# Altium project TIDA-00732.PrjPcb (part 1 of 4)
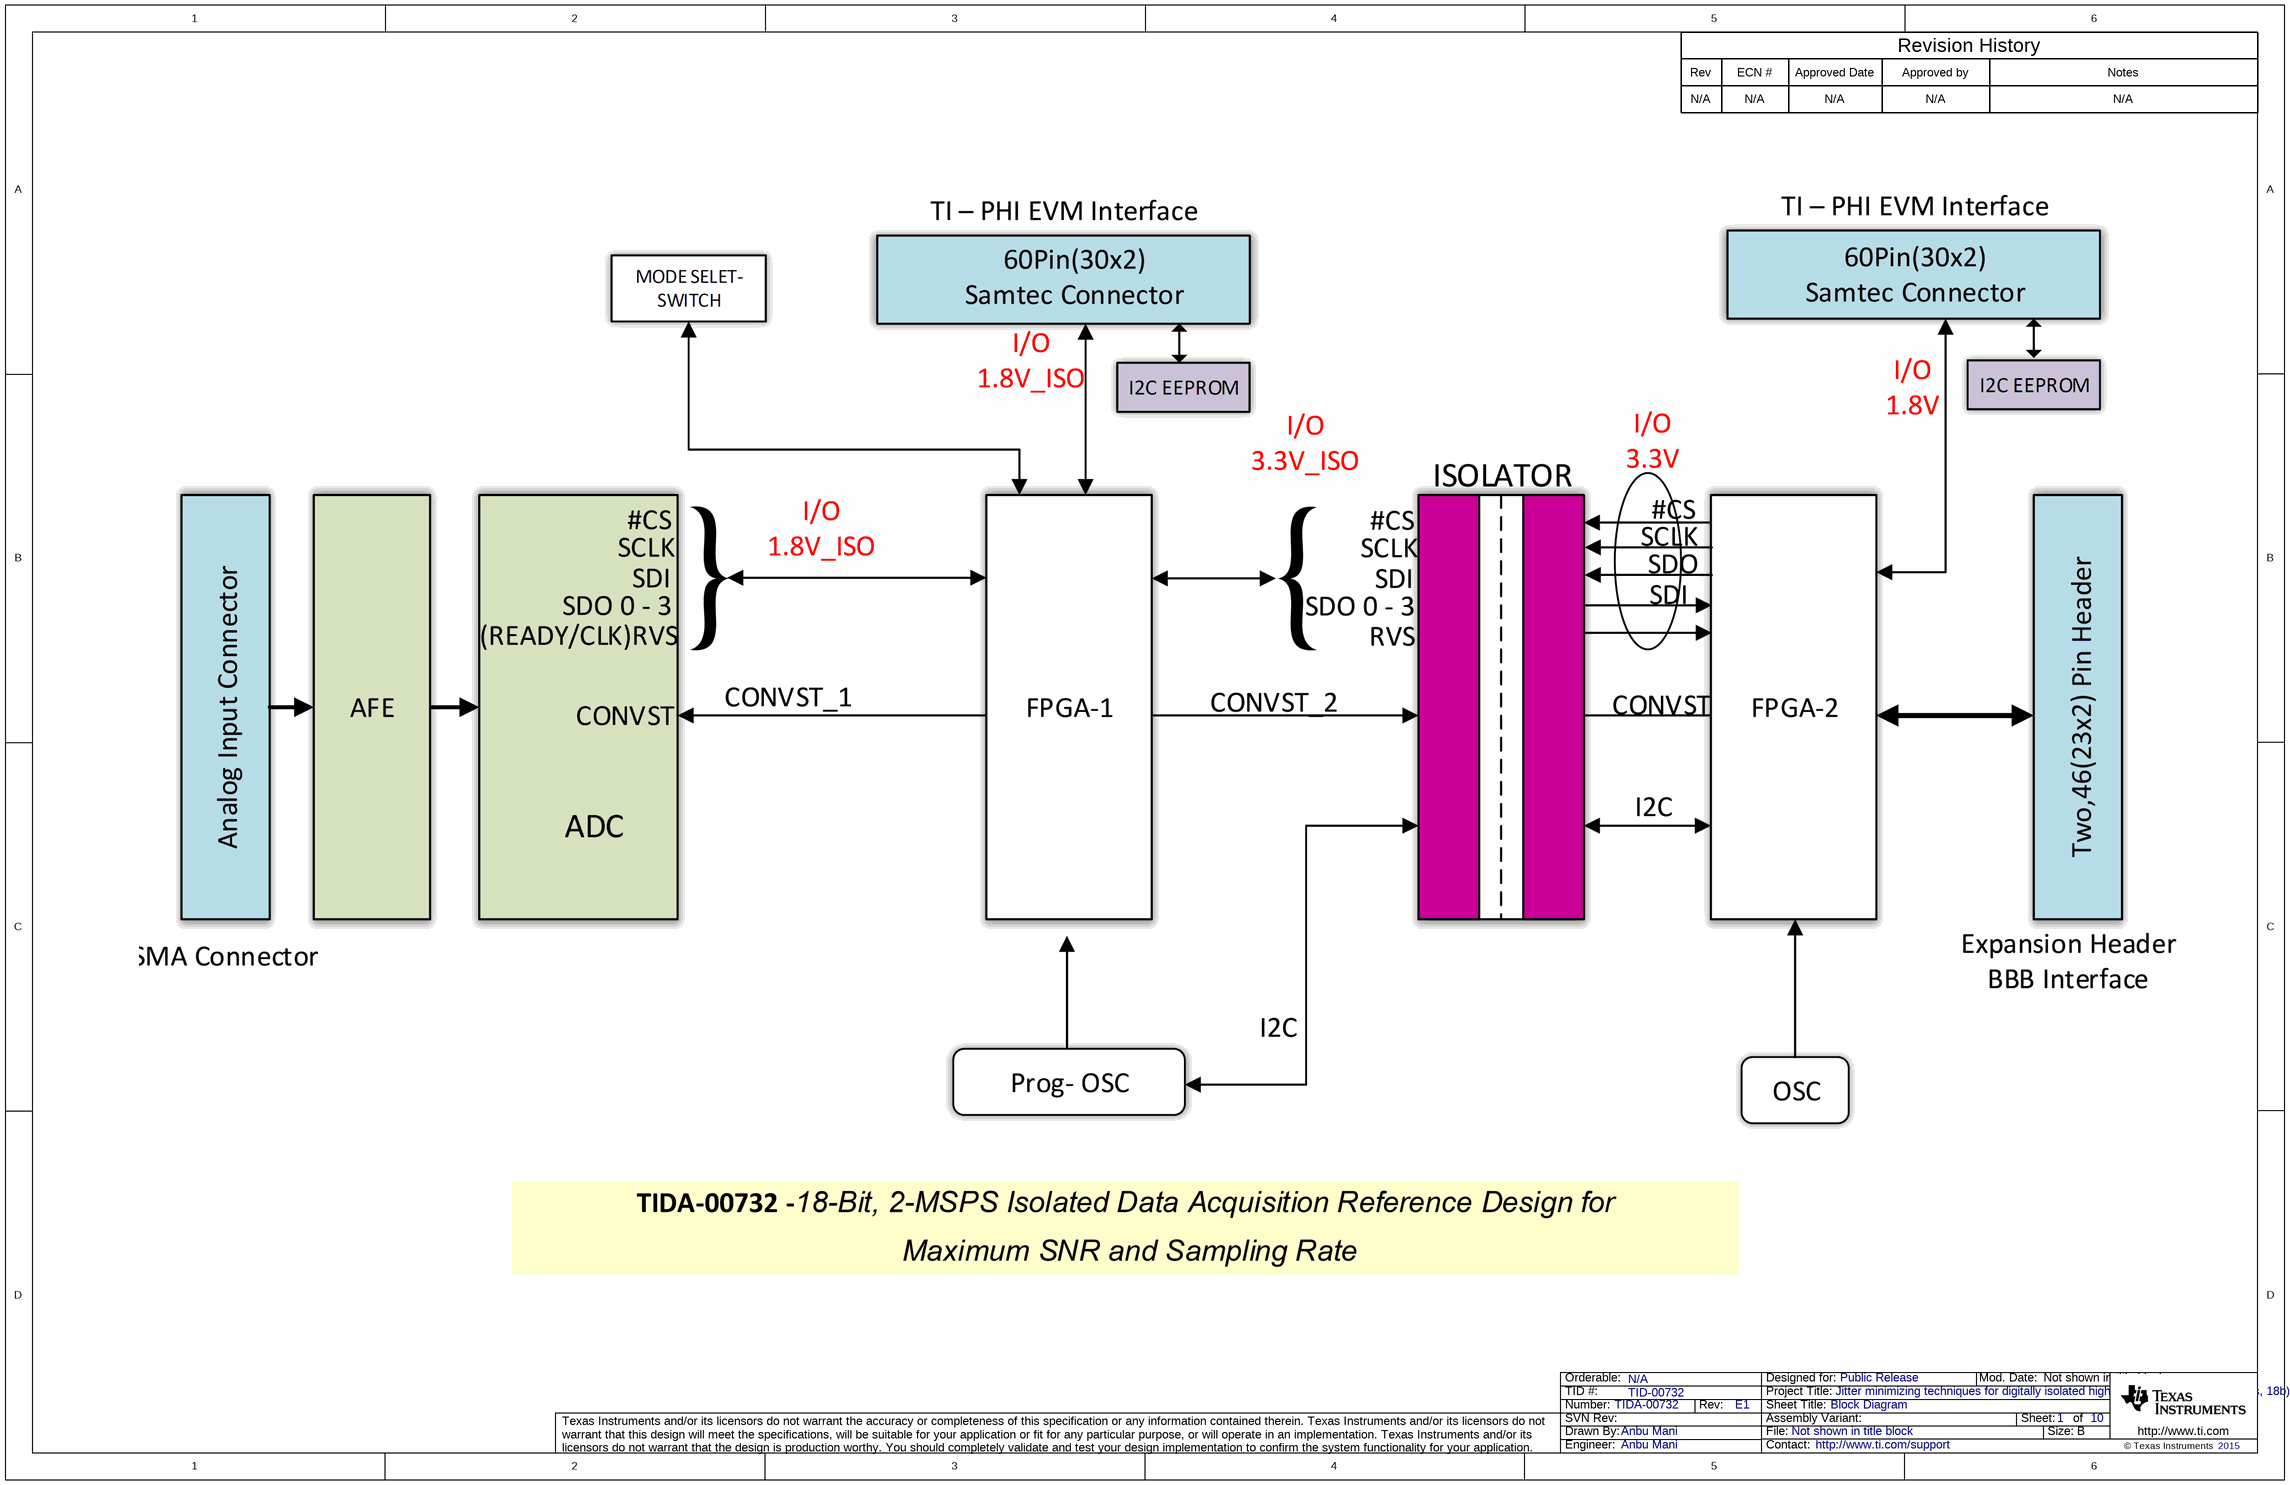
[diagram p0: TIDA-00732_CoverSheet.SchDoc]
CopyrightYear: 2015; EVM_Orderable: N/A; PCB_Layout: Avinash N; PCB_Rev: E1; PRJ_Customer: Public Release; PRJ_Engineer: Anbu Mani; PRJ_Number: TIDA-00732; PRJ_Title: Jitter minimizing techniques for digitally isolated high speed, high SNR (2.0 Msps, 18b) analog input DAQ; SCH_Rev: E1; TechSupport: http://www.ti.com/support; TID: TID-00732
10 sheets, 702 parts. Net scope: flat (ports and power ports of the same name join across sheets).
Board file: TIDA-00732.PcbDoc
Sheets:
  TIDA-00732_CoverSheet.SchDoc
  TIDA-00732_Connector.SchDoc
  TIDA-00732_Isolator.SchDoc
  TIDA-00732_ADC.SchDoc
  TIDA-00732_FPGA_1.SchDoc
  TIDA-00732_FPGA_2.SchDoc
  TIDA-00732_Pwr.SchDoc
  TIDA-00732_Pwr_Sense.SchDoc
  TIDA-00732_ADC_Ref_Select.SchDoc
  TIDA-00732_TID_Hardware.SchDoc

## Sheet TIDA-00732_CoverSheet.SchDoc: Block Diagram
size 431 x 279 mm; Date: Not shown in title block; ApprovedBy: Not shown in title block; CheckedBy: Not shown in title block; Author: Not shown in title block; CompanyName: Not shown in title block; DrawnBy: Anbu Mani; Engineer: Not shown in title block; Organization: Not shown in title block; Address1: Not shown in title block; Address2: Not shown in title block; Address3: Not shown in title block; Address4: Not shown in title block; DocumentNumber: 1; Revision: Use project parameter SCH_Rev; SheetNumber: 1; SheetTotal: 10; PageSetup: Record=PageOptions¦CenterHorizontal=True¦CenterVertical=True¦PrintScale=1.00¦XCorrection=1.00¦YCorrection=1.00¦PrintKind=0¦BorderSize=5000000¦LeftOffset=0¦BottomOffset=0¦Orientation=2¦PaperLength=1000¦PaperWidth=1000¦Scale=100¦PaperSource=15¦PrintQuality=600¦MediaType=1¦DitherType=10¦PaperKind=Letter¦PrintScaleMode=1

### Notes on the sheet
- Rev
- N/A
- ECN #
- Approved Date
- Approved by
- Revision History
- Notes

## Sheet TIDA-00732_Connector.SchDoc: Connector
size 431 x 279 mm; Date: Not shown in title block; ApprovedBy: Not shown in title block; CheckedBy: Not shown in title block; Author: Not shown in title block; CompanyName: Not shown in title block; DrawnBy: Anbu Mani; Engineer: Not shown in title block; Organization: Not shown in title block; Address1: Not shown in title block; Address2: Not shown in title block; Address3: Not shown in title block; Address4: Not shown in title block; DocumentNumber: 1; Revision: Use project parameter SCH_Rev; SheetNumber: 2; SheetTotal: 10; PageSetup: Record=PageOptions¦CenterHorizontal=True¦CenterVertical=True¦PrintScale=1.00¦XCorrection=1.00¦YCorrection=1.00¦PrintKind=0¦BorderSize=5000000¦LeftOffset=0¦BottomOffset=0¦Orientation=2¦PaperLength=1000¦PaperWidth=1000¦Scale=100¦PaperSource=15¦PrintQuality=600¦MediaType=1¦DitherType=10¦PaperKind=Letter¦PrintScaleMode=1
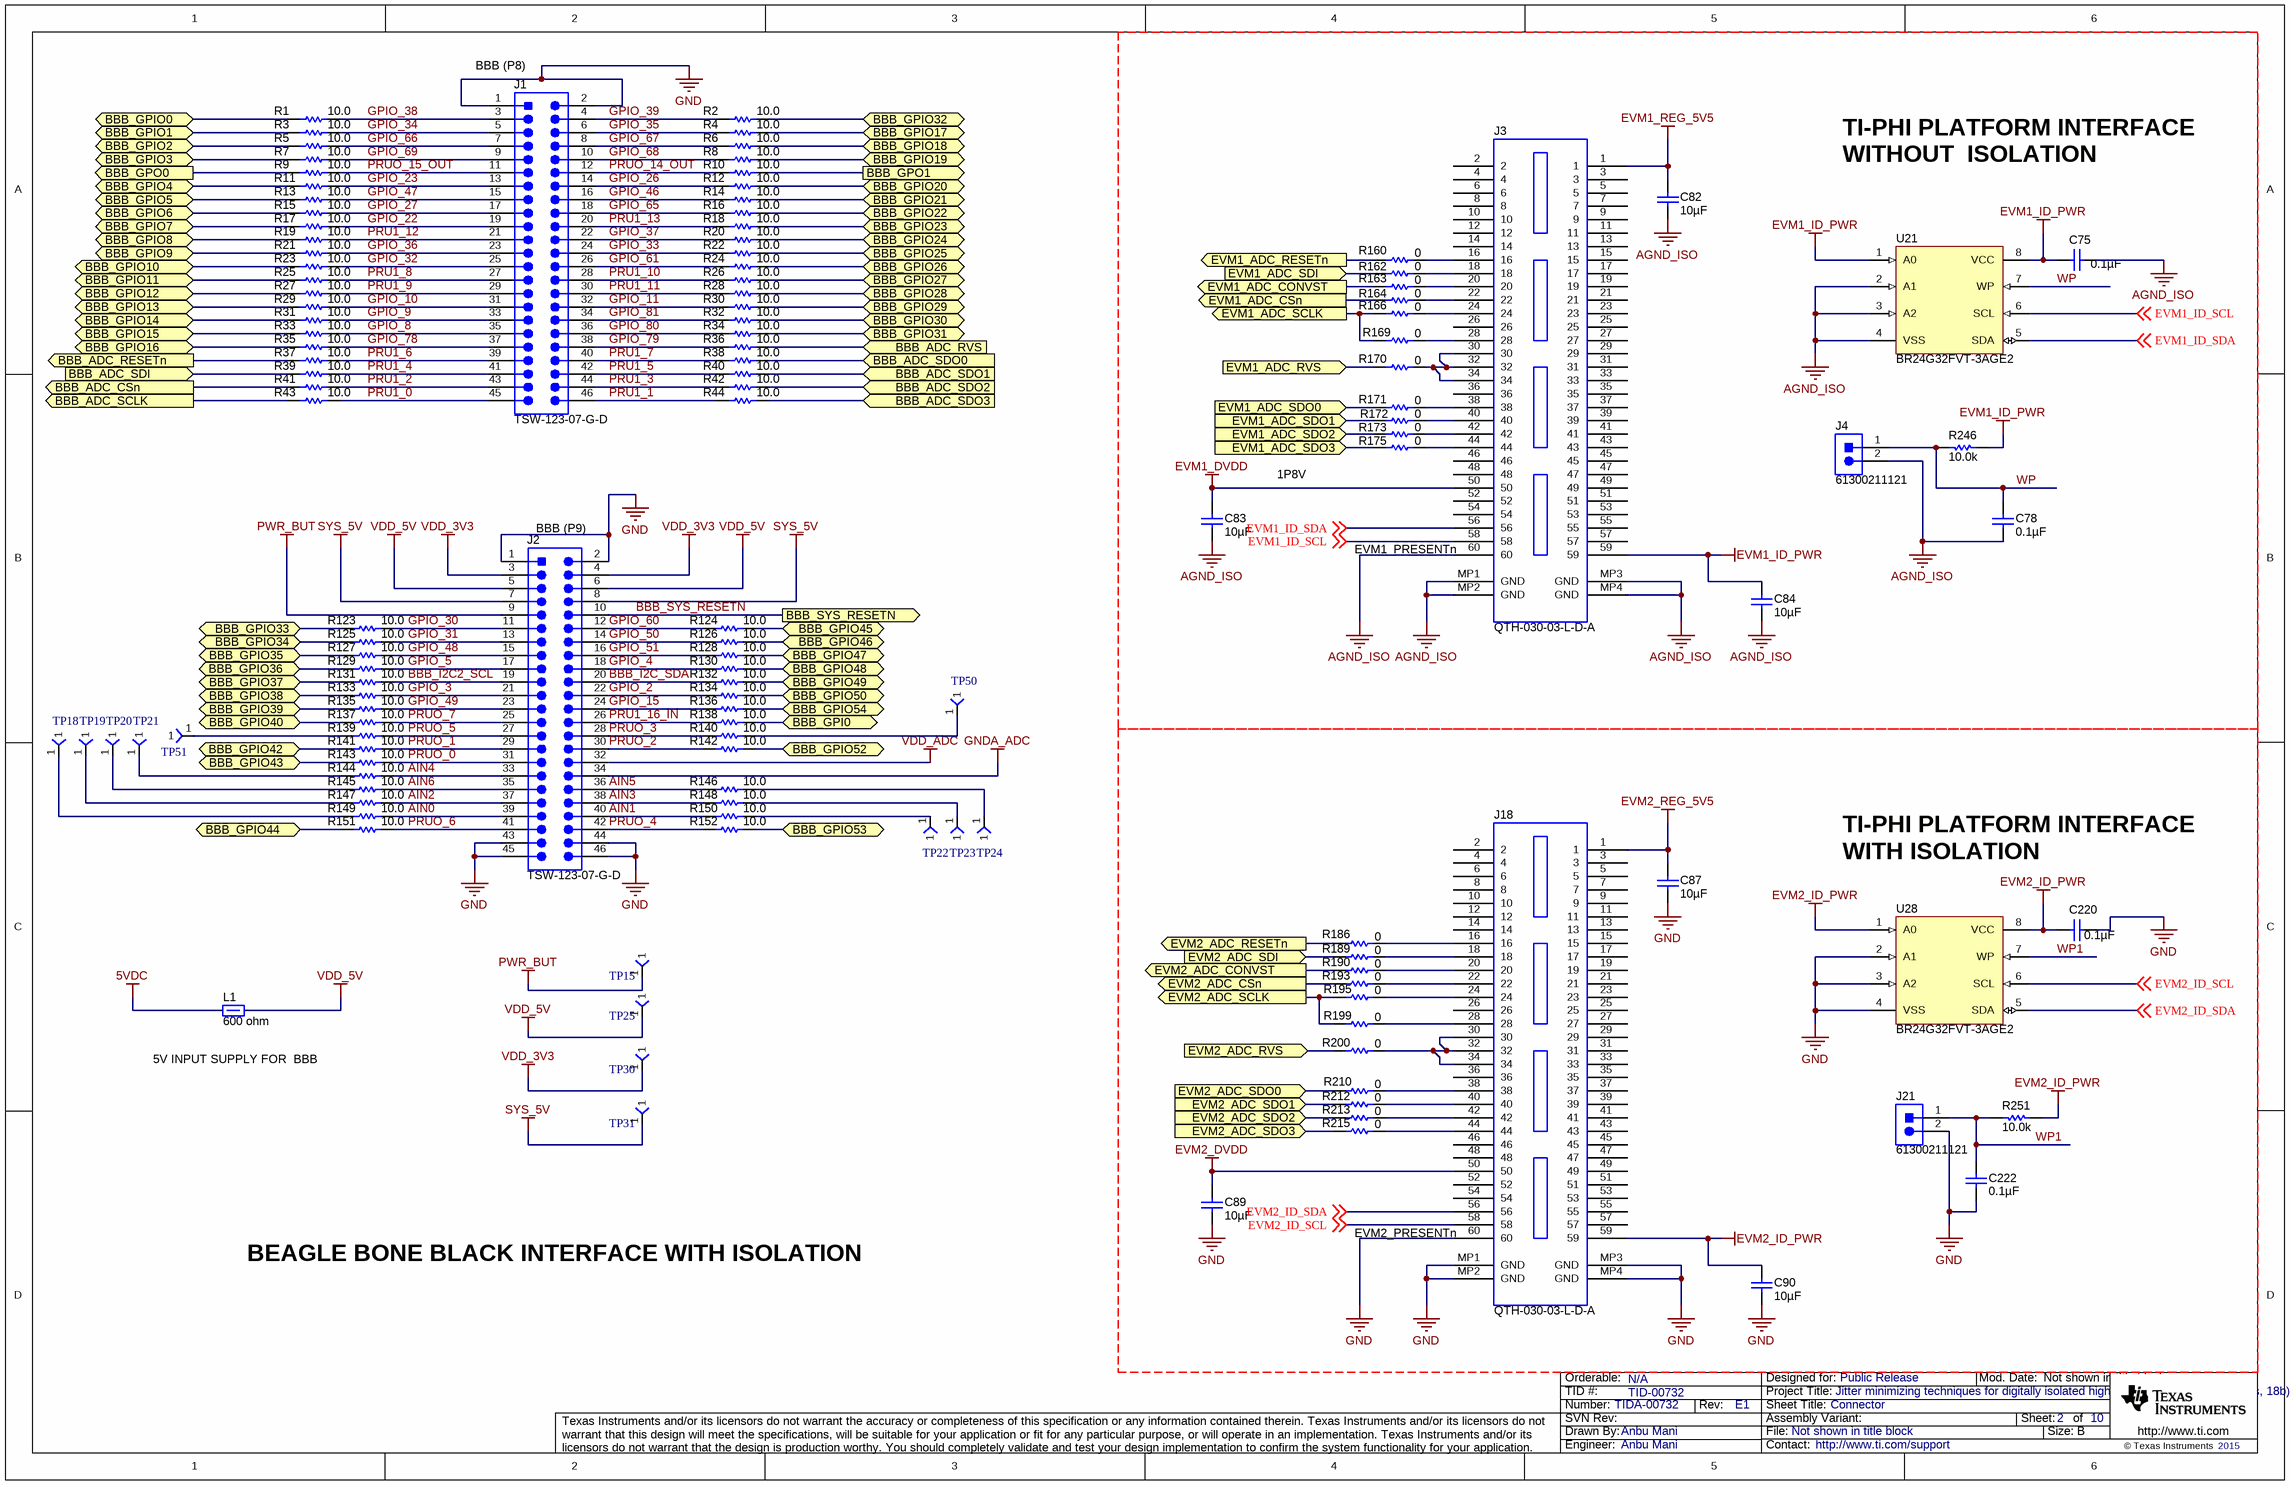
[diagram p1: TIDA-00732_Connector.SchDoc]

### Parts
C75  ValueDisplayed: 0.1µF  [0402]  (hidden comment: GRM155R71C104KA88D)
C78  ValueDisplayed: 0.1µF  [0402]  (hidden comment: GRM155R71C104KA88D)
C82  ValueDisplayed: 10µF  [0805_HV]  (hidden comment: GRM21BR71A106KE51L)
C83  ValueDisplayed: 10µF  [0805_HV]  (hidden comment: GRM21BR71A106KE51L)
C84  ValueDisplayed: 10µF  [0805_HV]  (hidden comment: GRM21BR71A106KE51L)
C87  ValueDisplayed: 10µF  [0805_HV]  (hidden comment: GRM21BR71A106KE51L)
C89  ValueDisplayed: 10µF  [0805_HV]  (hidden comment: GRM21BR71A106KE51L)
C90  ValueDisplayed: 10µF  [0805_HV]  (hidden comment: GRM21BR71A106KE51L)
C220  ValueDisplayed: 0.1µF  [0402]  (hidden comment: GRM155R71C104KA88D)
C222  ValueDisplayed: 0.1µF  [0402]  (hidden comment: GRM155R71C104KA88D)
J1  TSW-123-07-G-D  [Samtec_TSW-123-07-x-D]
J2  TSW-123-07-G-D  [Samtec_TSW-123-07-x-D]
J3  QTH-030-03-L-D-A  [Samtec_QTH-030-01-x-D-A]
J4  61300211121  [WURTH_61300211121]
J18  QTH-030-03-L-D-A  [Samtec_QTH-030-01-x-D-A]
J21  61300211121  [WURTH_61300211121]
L1  value 600 ohm  [0805_HV]  (hidden comment: HZ0805E601R-10)
R1  ValueDisplayed: 10.0  [0402]  (hidden comment: CRCW040210R0FKED)
R2  ValueDisplayed: 10.0  [0402]  (hidden comment: CRCW040210R0FKED)
R3  ValueDisplayed: 10.0  [0402]  (hidden comment: CRCW040210R0FKED)
R4  ValueDisplayed: 10.0  [0402]  (hidden comment: CRCW040210R0FKED)
R5  ValueDisplayed: 10.0  [0402]  (hidden comment: CRCW040210R0FKED)
R6  ValueDisplayed: 10.0  [0402]  (hidden comment: CRCW040210R0FKED)
R7  ValueDisplayed: 10.0  [0402]  (hidden comment: CRCW040210R0FKED)
R8  ValueDisplayed: 10.0  [0402]  (hidden comment: CRCW040210R0FKED)
R9  ValueDisplayed: 10.0  [0402]  (hidden comment: CRCW040210R0FKED)
R10  ValueDisplayed: 10.0  [0402]  (hidden comment: CRCW040210R0FKED)
R11  ValueDisplayed: 10.0  [0402]  (hidden comment: CRCW040210R0FKED)
R12  ValueDisplayed: 10.0  [0402]  (hidden comment: CRCW040210R0FKED)
R13  ValueDisplayed: 10.0  [0402]  (hidden comment: CRCW040210R0FKED)
R14  ValueDisplayed: 10.0  [0402]  (hidden comment: CRCW040210R0FKED)
R15  ValueDisplayed: 10.0  [0402]  (hidden comment: CRCW040210R0FKED)
R16  ValueDisplayed: 10.0  [0402]  (hidden comment: CRCW040210R0FKED)
R17  ValueDisplayed: 10.0  [0402]  (hidden comment: CRCW040210R0FKED)
R18  ValueDisplayed: 10.0  [0402]  (hidden comment: CRCW040210R0FKED)
R19  ValueDisplayed: 10.0  [0402]  (hidden comment: CRCW040210R0FKED)
R20  ValueDisplayed: 10.0  [0402]  (hidden comment: CRCW040210R0FKED)
R21  ValueDisplayed: 10.0  [0402]  (hidden comment: CRCW040210R0FKED)
R22  ValueDisplayed: 10.0  [0402]  (hidden comment: CRCW040210R0FKED)
R23  ValueDisplayed: 10.0  [0402]  (hidden comment: CRCW040210R0FKED)
R24  ValueDisplayed: 10.0  [0402]  (hidden comment: CRCW040210R0FKED)
R25  ValueDisplayed: 10.0  [0402]  (hidden comment: CRCW040210R0FKED)
R26  ValueDisplayed: 10.0  [0402]  (hidden comment: CRCW040210R0FKED)
R27  ValueDisplayed: 10.0  [0402]  (hidden comment: CRCW040210R0FKED)
R28  ValueDisplayed: 10.0  [0402]  (hidden comment: CRCW040210R0FKED)
R29  ValueDisplayed: 10.0  [0402]  (hidden comment: CRCW040210R0FKED)
R30  ValueDisplayed: 10.0  [0402]  (hidden comment: CRCW040210R0FKED)
R31  ValueDisplayed: 10.0  [0402]  (hidden comment: CRCW040210R0FKED)
R32  ValueDisplayed: 10.0  [0402]  (hidden comment: CRCW040210R0FKED)
R33  ValueDisplayed: 10.0  [0402]  (hidden comment: CRCW040210R0FKED)
R34  ValueDisplayed: 10.0  [0402]  (hidden comment: CRCW040210R0FKED)
R35  ValueDisplayed: 10.0  [0402]  (hidden comment: CRCW040210R0FKED)
R36  ValueDisplayed: 10.0  [0402]  (hidden comment: CRCW040210R0FKED)
R37  ValueDisplayed: 10.0  [0402]  (hidden comment: CRCW040210R0FKED)
R38  ValueDisplayed: 10.0  [0402]  (hidden comment: CRCW040210R0FKED)
R39  ValueDisplayed: 10.0  [0402]  (hidden comment: CRCW040210R0FKED)
R40  ValueDisplayed: 10.0  [0402]  (hidden comment: CRCW040210R0FKED)
R41  ValueDisplayed: 10.0  [0402]  (hidden comment: CRCW040210R0FKED)
R42  ValueDisplayed: 10.0  [0402]  (hidden comment: CRCW040210R0FKED)
R43  ValueDisplayed: 10.0  [0402]  (hidden comment: CRCW040210R0FKED)
R44  ValueDisplayed: 10.0  [0402]  (hidden comment: CRCW040210R0FKED)
R123  ValueDisplayed: 10.0  [0402]  (hidden comment: CRCW040210R0FKED)
R124  ValueDisplayed: 10.0  [0402]  (hidden comment: CRCW040210R0FKED)
R125  ValueDisplayed: 10.0  [0402]  (hidden comment: CRCW040210R0FKED)
R126  ValueDisplayed: 10.0  [0402]  (hidden comment: CRCW040210R0FKED)
R127  ValueDisplayed: 10.0  [0402]  (hidden comment: CRCW040210R0FKED)
R128  ValueDisplayed: 10.0  [0402]  (hidden comment: CRCW040210R0FKED)
R129  ValueDisplayed: 10.0  [0402]  (hidden comment: CRCW040210R0FKED)
R130  ValueDisplayed: 10.0  [0402]  (hidden comment: CRCW040210R0FKED)
R131  ValueDisplayed: 10.0  [0402]  (hidden comment: CRCW040210R0FKED)
R132  ValueDisplayed: 10.0  [0402]  (hidden comment: CRCW040210R0FKED)
R133  ValueDisplayed: 10.0  [0402]  (hidden comment: CRCW040210R0FKED)
R134  ValueDisplayed: 10.0  [0402]  (hidden comment: CRCW040210R0FKED)
R135  ValueDisplayed: 10.0  [0402]  (hidden comment: CRCW040210R0FKED)
R136  ValueDisplayed: 10.0  [0402]  (hidden comment: CRCW040210R0FKED)
R137  ValueDisplayed: 10.0  [0402]  (hidden comment: CRCW040210R0FKED)
R138  ValueDisplayed: 10.0  [0402]  (hidden comment: CRCW040210R0FKED)
R139  ValueDisplayed: 10.0  [0402]  (hidden comment: CRCW040210R0FKED)
R140  ValueDisplayed: 10.0  [0402]  (hidden comment: CRCW040210R0FKED)
R141  ValueDisplayed: 10.0  [0402]  (hidden comment: CRCW040210R0FKED)
R142  ValueDisplayed: 10.0  [0402]  (hidden comment: CRCW040210R0FKED)
R143  ValueDisplayed: 10.0  [0402]  (hidden comment: CRCW040210R0FKED)
R144  ValueDisplayed: 10.0  [0402]  (hidden comment: CRCW040210R0FKED)
R145  ValueDisplayed: 10.0  [0402]  (hidden comment: CRCW040210R0FKED)
R146  ValueDisplayed: 10.0  [0402]  (hidden comment: CRCW040210R0FKED)
R147  ValueDisplayed: 10.0  [0402]  (hidden comment: CRCW040210R0FKED)
R148  ValueDisplayed: 10.0  [0402]  (hidden comment: CRCW040210R0FKED)
R149  ValueDisplayed: 10.0  [0402]  (hidden comment: CRCW040210R0FKED)
R150  ValueDisplayed: 10.0  [0402]  (hidden comment: CRCW040210R0FKED)
R151  ValueDisplayed: 10.0  [0402]  (hidden comment: CRCW040210R0FKED)
R152  ValueDisplayed: 10.0  [0402]  (hidden comment: CRCW040210R0FKED)
R160  ValueDisplayed: 0  [0402]  (hidden comment: ERJ-2GE0R00X)
R162  ValueDisplayed: 0  [0402]  (hidden comment: ERJ-2GE0R00X)
R163  ValueDisplayed: 0  [0402]  (hidden comment: ERJ-2GE0R00X)
R164  ValueDisplayed: 0  [0402]  (hidden comment: ERJ-2GE0R00X)
R166  ValueDisplayed: 0  [0402]  (hidden comment: ERJ-2GE0R00X)
R169  ValueDisplayed: 0  [0402]  (hidden comment: ERJ-2GE0R00X)
R170  ValueDisplayed: 0  [0402]  (hidden comment: ERJ-2GE0R00X)
R171  ValueDisplayed: 0  [0402]  (hidden comment: ERJ-2GE0R00X)
R172  ValueDisplayed: 0  [0402]  (hidden comment: ERJ-2GE0R00X)
R173  ValueDisplayed: 0  [0402]  (hidden comment: ERJ-2GE0R00X)
R175  ValueDisplayed: 0  [0402]  (hidden comment: ERJ-2GE0R00X)
R186  ValueDisplayed: 0  [0402]  (hidden comment: ERJ-2GE0R00X)
R189  ValueDisplayed: 0  [0402]  (hidden comment: ERJ-2GE0R00X)
R190  ValueDisplayed: 0  [0402]  (hidden comment: ERJ-2GE0R00X)
R193  ValueDisplayed: 0  [0402]  (hidden comment: ERJ-2GE0R00X)
R195  ValueDisplayed: 0  [0402]  (hidden comment: ERJ-2GE0R00X)
R199  ValueDisplayed: 0  [0402]  (hidden comment: ERJ-2GE0R00X)
R200  ValueDisplayed: 0  [0402]  (hidden comment: ERJ-2GE0R00X)
R210  ValueDisplayed: 0  [0402]  (hidden comment: ERJ-2GE0R00X)
R212  ValueDisplayed: 0  [0402]  (hidden comment: ERJ-2GE0R00X)
R213  ValueDisplayed: 0  [0402]  (hidden comment: ERJ-2GE0R00X)
R215  ValueDisplayed: 0  [0402]  (hidden comment: ERJ-2GE0R00X)
R246  ValueDisplayed: 10.0k  [0603]  (hidden comment: CRCW060310K0FKEA)
R251  ValueDisplayed: 10.0k  [0603]  (hidden comment: CRCW060310K0FKEA)
TP15  TP-025-SMT  [TP_25MIL-SMT]  (value not drawn)
TP18  TP-025-SMT  [TP_25MIL-SMT]  (value not drawn)
TP19  TP-025-SMT  [TP_25MIL-SMT]  (value not drawn)
TP20  TP-025-SMT  [TP_25MIL-SMT]  (value not drawn)
TP21  TP-025-SMT  [TP_25MIL-SMT]  (value not drawn)
TP22  TP-025-SMT  [TP_25MIL-SMT]  (value not drawn)
TP23  TP-025-SMT  [TP_25MIL-SMT]  (value not drawn)
TP24  TP-025-SMT  [TP_25MIL-SMT]  (value not drawn)
TP25  TP-025-SMT  [TP_25MIL-SMT]  (value not drawn)
TP30  TP-025-SMT  [TP_25MIL-SMT]  (value not drawn)
TP31  TP-025-SMT  [TP_25MIL-SMT]  (value not drawn)
TP50  TP-025-SMT  [TP_25MIL-SMT]  (value not drawn)
TP51  TP-025-SMT  [TP_25MIL-SMT]  (value not drawn)
U21  BR24G32FVT-3AGE2  [TSOP65P640X120-8N]
U28  BR24G32FVT-3AGE2  [TSOP65P640X120-8N]

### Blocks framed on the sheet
EVM2_PRESENTn: C87 C89 C90 C220 C222 J18 J21 R186 R189 R190 R193 R195 R199 R200 R210 R212 R213 R215 R251 U28

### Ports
BBB_ADC_CSn (out), BBB_ADC_RESETn (out), BBB_ADC_RVS (in), BBB_ADC_SCLK (out), BBB_ADC_SDI (in), BBB_ADC_SDO0 (in), BBB_ADC_SDO1 (in), BBB_ADC_SDO2 (in), BBB_ADC_SDO3 (in), BBB_GPI0 (bidir), BBB_GPIO0 (bidir), BBB_GPIO1 (bidir), BBB_GPIO2 (bidir), BBB_GPIO3 (bidir), BBB_GPIO4 (bidir), BBB_GPIO5 (bidir), BBB_GPIO6 (bidir), BBB_GPIO7 (bidir), BBB_GPIO8 (bidir), BBB_GPIO9 (bidir), BBB_GPIO10 (bidir), BBB_GPIO11 (bidir), BBB_GPIO12 (bidir), BBB_GPIO13 (bidir), BBB_GPIO14 (bidir), BBB_GPIO15 (bidir), BBB_GPIO16 (bidir), BBB_GPIO17 (bidir), BBB_GPIO18 (bidir), BBB_GPIO19 (bidir), BBB_GPIO20 (bidir), BBB_GPIO21 (bidir), BBB_GPIO22 (bidir), BBB_GPIO23 (bidir), BBB_GPIO24 (bidir), BBB_GPIO25 (bidir), BBB_GPIO26 (bidir), BBB_GPIO27 (bidir), BBB_GPIO28 (bidir), BBB_GPIO29 (bidir), BBB_GPIO30 (bidir), BBB_GPIO31 (bidir), BBB_GPIO32 (bidir), BBB_GPIO33 (bidir), BBB_GPIO34 (bidir), BBB_GPIO35 (bidir), BBB_GPIO36 (bidir), BBB_GPIO37 (bidir), BBB_GPIO38 (bidir), BBB_GPIO39 (bidir), BBB_GPIO40 (bidir), BBB_GPIO42 (bidir), BBB_GPIO43 (bidir), BBB_GPIO44 (bidir), BBB_GPIO45 (bidir), BBB_GPIO46 (bidir), BBB_GPIO47 (bidir), BBB_GPIO48 (bidir), BBB_GPIO49 (bidir), BBB_GPIO50 (bidir), BBB_GPIO52 (bidir), BBB_GPIO53 (bidir), BBB_GPIO54 (bidir), BBB_GPO0 (out), BBB_GPO1 (out), BBB_SYS_RESETN (out), EVM1_ADC_CONVST (out), EVM1_ADC_CSn (out), EVM1_ADC_RESETn (out), EVM1_ADC_RVS (in), EVM1_ADC_SCLK (out), EVM1_ADC_SDI (in), EVM1_ADC_SDO0 (in), EVM1_ADC_SDO1 (in), EVM1_ADC_SDO2 (in), EVM1_ADC_SDO3 (in), EVM2_ADC_CONVST (out), EVM2_ADC_CSn (out), EVM2_ADC_RESETn (out), EVM2_ADC_RVS (in), EVM2_ADC_SCLK (out), EVM2_ADC_SDI (in), EVM2_ADC_SDO0 (in), EVM2_ADC_SDO1 (in), EVM2_ADC_SDO2 (in), EVM2_ADC_SDO3 (in)

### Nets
5VDC: L1.1
AGND_ISO: C75.1 C78.1 C82.2 C83.2 C84.2 J3.60 J3.MP1(GND) J3.MP2(GND) J3.MP3(GND) J3.MP4(GND) J4.2 U21.2(A1) U21.3(A2) U21.4(VSS)
EVM1_DVDD: C83.1 J3.50
EVM1_ID_PWR: C75.2 C84.1 J3.59 R246.2 U21.1(A0) U21.8(VCC)
EVM1_REG_5V5: C82.1 J3.1
EVM2_DVDD: C89.1 J18.50
EVM2_ID_PWR: C90.1 C220.2 J18.59 R251.2 U28.1(A0) U28.8(VCC)
EVM2_REG_5V5: C87.1 J18.1
GND: C87.2 C89.2 C90.2 C220.1 C222.1 J1.1 J1.2 J2.1 J2.2 J2.43 J2.44 J2.45 J2.46 J18.60 J18.MP1(GND) J18.MP2(GND) J18.MP3(GND) J18.MP4(GND) J21.2 U28.2(A1) U28.3(A2) U28.4(VSS)
GNDA_ADC: J2.34
PWR_BUT: J2.9 TP15.1
SYS_5V: J2.7 J2.8 TP31.1
VDD_3V3: J2.3 J2.4 TP30.1
VDD_5V: J2.5 J2.6 L1.2 TP25.1
VDD_ADC: J2.32
AIN0: J2.39 R149.2
AIN1: J2.40 R150.1
AIN2: J2.37 R147.2
AIN3: J2.38 R148.1
AIN4: J2.33 R144.2
AIN5: J2.36 R146.1
AIN6: J2.35 R145.2
BBB_ADC_CSn: R41.1 ; port BBB_ADC_CSn
BBB_ADC_RESETn: R37.1 ; port BBB_ADC_RESETn
BBB_ADC_RVS: R36.2 ; port BBB_ADC_RVS
BBB_ADC_SCLK: R43.1 ; port BBB_ADC_SCLK
BBB_ADC_SDI: R39.1 ; port BBB_ADC_SDI
BBB_ADC_SDO0: R38.2 ; port BBB_ADC_SDO0
BBB_ADC_SDO1: R40.2 ; port BBB_ADC_SDO1
BBB_ADC_SDO2: R42.2 ; port BBB_ADC_SDO2
BBB_ADC_SDO3: R44.2 ; port BBB_ADC_SDO3
BBB_GPI0: R138.2 ; port BBB_GPI0
BBB_GPIO0: R1.1 ; port BBB_GPIO0
BBB_GPIO1: R3.1 ; port BBB_GPIO1
BBB_GPIO2: R5.1 ; port BBB_GPIO2
BBB_GPIO3: R7.1 ; port BBB_GPIO3
BBB_GPIO4: R11.1 ; port BBB_GPIO4
BBB_GPIO5: R13.1 ; port BBB_GPIO5
BBB_GPIO6: R15.1 ; port BBB_GPIO6
BBB_GPIO7: R17.1 ; port BBB_GPIO7
BBB_GPIO8: R19.1 ; port BBB_GPIO8
BBB_GPIO9: R21.1 ; port BBB_GPIO9
BBB_GPIO10: R23.1 ; port BBB_GPIO10
BBB_GPIO11: R25.1 ; port BBB_GPIO11
BBB_GPIO12: R27.1 ; port BBB_GPIO12
BBB_GPIO13: R29.1 ; port BBB_GPIO13
BBB_GPIO14: R31.1 ; port BBB_GPIO14
BBB_GPIO15: R33.1 ; port BBB_GPIO15
BBB_GPIO16: R35.1 ; port BBB_GPIO16
BBB_GPIO17: R4.2 ; port BBB_GPIO17
BBB_GPIO18: R6.2 ; port BBB_GPIO18
BBB_GPIO19: R8.2 ; port BBB_GPIO19
BBB_GPIO20: R12.2 ; port BBB_GPIO20
BBB_GPIO21: R14.2 ; port BBB_GPIO21
BBB_GPIO22: R16.2 ; port BBB_GPIO22
BBB_GPIO23: R18.2 ; port BBB_GPIO23
BBB_GPIO24: R20.2 ; port BBB_GPIO24
BBB_GPIO25: R22.2 ; port BBB_GPIO25
BBB_GPIO26: R24.2 ; port BBB_GPIO26
BBB_GPIO27: R26.2 ; port BBB_GPIO27
BBB_GPIO28: R28.2 ; port BBB_GPIO28
BBB_GPIO29: R30.2 ; port BBB_GPIO29
BBB_GPIO30: R32.2 ; port BBB_GPIO30
BBB_GPIO31: R34.2 ; port BBB_GPIO31
BBB_GPIO32: R2.2 ; port BBB_GPIO32
BBB_GPIO35: R127.1 ; port BBB_GPIO35
BBB_GPIO36: R129.1 ; port BBB_GPIO36
BBB_GPIO37: R131.1 ; port BBB_GPIO37
BBB_GPIO38: R133.1 ; port BBB_GPIO38
BBB_GPIO39: R135.1 ; port BBB_GPIO39
BBB_GPIO40: R137.1 ; port BBB_GPIO40
BBB_GPIO42: R141.1 ; port BBB_GPIO42
BBB_GPIO43: R143.1 ; port BBB_GPIO43
BBB_GPIO44: R151.1 ; port BBB_GPIO44
BBB_GPIO47: R128.2 ; port BBB_GPIO47
BBB_GPIO48: R130.2 ; port BBB_GPIO48
BBB_GPIO49: R132.2 ; port BBB_GPIO49
BBB_GPIO50: R134.2 ; port BBB_GPIO50
BBB_GPIO52: R142.2 ; port BBB_GPIO52
BBB_GPIO53: R152.2 ; port BBB_GPIO53
BBB_GPIO54: R136.2 ; port BBB_GPIO54
BBB_GPO0: R9.1 ; port BBB_GPO0
BBB_GPO1: R10.2 ; port BBB_GPO1
BBB_I2C2_SCL: J2.19 R131.2
BBB_I2C_SDA: J2.20 R132.1
BBB_SYS_RESETN: J2.10 ; port BBB_SYS_RESETN
EVM1_ADC_CONVST: R163.1 ; port EVM1_ADC_CONVST
EVM1_ADC_CSn: R164.1 ; port EVM1_ADC_CSn
EVM1_ADC_RESETn: R160.1 ; port EVM1_ADC_RESETn
EVM1_ADC_RVS: R170.1 ; port EVM1_ADC_RVS
EVM1_ADC_SCLK: R166.1 R169.1 ; port EVM1_ADC_SCLK
EVM1_ADC_SDI: R162.1 ; port EVM1_ADC_SDI
EVM1_ADC_SDO0: R171.1 ; port EVM1_ADC_SDO0
EVM1_ADC_SDO1: R172.1 ; port EVM1_ADC_SDO1
EVM1_ADC_SDO2: R173.1 ; port EVM1_ADC_SDO2
EVM1_ADC_SDO3: R175.1 ; port EVM1_ADC_SDO3
EVM1_ID_SCL: J3.58 U21.6(SCL) ; off-sheet EVM1_ID_SCL
EVM1_ID_SDA: J3.56 U21.5(SDA) ; off-sheet EVM1_ID_SDA
EVM2_ADC_CONVST: R190.1 ; port EVM2_ADC_CONVST
EVM2_ADC_CSn: R193.1 ; port EVM2_ADC_CSn
EVM2_ADC_RESETn: R186.1 ; port EVM2_ADC_RESETn
EVM2_ADC_RVS: R200.1 ; port EVM2_ADC_RVS
EVM2_ADC_SCLK: R195.1 R199.1 ; port EVM2_ADC_SCLK
EVM2_ADC_SDI: R189.1 ; port EVM2_ADC_SDI
EVM2_ADC_SDO0: R210.1 ; port EVM2_ADC_SDO0
EVM2_ADC_SDO1: R212.1 ; port EVM2_ADC_SDO1
EVM2_ADC_SDO2: R213.1 ; port EVM2_ADC_SDO2
EVM2_ADC_SDO3: R215.1 ; port EVM2_ADC_SDO3
EVM2_ID_SCL: J18.58 U28.6(SCL) ; off-sheet EVM2_ID_SCL
EVM2_ID_SDA: J18.56 U28.5(SDA) ; off-sheet EVM2_ID_SDA
FSTS0_LED: R123.1 ; port BBB_GPIO33
FSTS1_LED: R124.2 ; port BBB_GPIO45
FSTS2_LED: R125.1 ; port BBB_GPIO34
FSTS3_LED: R126.2 ; port BBB_GPIO46
GPIO_2: J2.22 R134.1
GPIO_3: J2.21 R133.2
GPIO_4: J2.18 R130.1
GPIO_5: J2.17 R129.2
GPIO_8: J1.35 R33.2
GPIO_9: J1.33 R31.2
GPIO_10: J1.31 R29.2
GPIO_11: J1.32 R30.1
GPIO_15: J2.24 R136.1
GPIO_22: J1.19 R17.2
GPIO_23: J1.13 R11.2
GPIO_26: J1.14 R12.1
GPIO_27: J1.17 R15.2
GPIO_30: J2.11 R123.2
GPIO_31: J2.13 R125.2
GPIO_32: J1.25 R23.2
GPIO_33: J1.24 R22.1
GPIO_34: J1.5 R3.2
GPIO_35: J1.6 R4.1
GPIO_36: J1.23 R21.2
GPIO_37: J1.22 R20.1
GPIO_38: J1.3 R1.2
GPIO_39: J1.4 R2.1
GPIO_46: J1.16 R14.1
GPIO_47: J1.15 R13.2
GPIO_48: J2.15 R127.2
GPIO_49: J2.23 R135.2
GPIO_50: J2.14 R126.1
GPIO_51: J2.16 R128.1
GPIO_60: J2.12 R124.1
GPIO_61: J1.26 R24.1
GPIO_65: J1.18 R16.1
GPIO_66: J1.7 R5.2
GPIO_67: J1.8 R6.1
GPIO_68: J1.10 R8.1
GPIO_69: J1.9 R7.2
GPIO_78: J1.37 R35.2
GPIO_79: J1.38 R36.1
GPIO_80: J1.36 R34.1
GPIO_81: J1.34 R32.1
PRU1_0: J1.45 R43.2
PRU1_1: J1.46 R44.1
PRU1_2: J1.43 R41.2
PRU1_3: J1.44 R42.1
PRU1_4: J1.41 R39.2
PRU1_5: J1.42 R40.1
PRU1_6: J1.39 R37.2
PRU1_7: J1.40 R38.1
PRU1_8: J1.27 R25.2
PRU1_9: J1.29 R27.2
PRU1_10: J1.28 R26.1
PRU1_11: J1.30 R28.1
PRU1_12: J1.21 R19.2
PRU1_13: J1.20 R18.1
PRU1_16_IN: J2.26 R138.1
PRUO_0: J2.31 R143.2
PRUO_1: J2.29 R141.2
PRUO_2: J2.30 R142.1
PRUO_3: J2.28 R140.1
PRUO_4: J2.42 R152.1
PRUO_5: J2.27 R139.2
PRUO_6: J2.41 R151.2
PRUO_7: J2.25 R137.2
PRUO_14_OUT: J1.12 R10.1
PRUO_15_OUT: J1.11 R9.2
WP: C78.2 J4.1 R246.1 U21.7(WP)
WP1: C222.2 J21.1 R251.1 U28.7(WP)
NetJ3_16: J3.16 R160.2
NetJ3_18: J3.18 R162.2
NetJ3_20: J3.20 R163.2
NetJ3_22: J3.22 R164.2
NetJ3_24: J3.24 R166.2
NetJ3_28: J3.28 R169.2
NetJ3_30: J3.30 J3.32 J3.34 R170.2
NetJ3_38: J3.38 R171.2
NetJ3_40: J3.40 R172.2
NetJ3_42: J3.42 R173.2
NetJ3_44: J3.44 R175.2
NetJ18_16: J18.16 R186.2
NetJ18_18: J18.18 R189.2
NetJ18_20: J18.20 R190.2
NetJ18_22: J18.22 R193.2
NetJ18_24: J18.24 R195.2
NetJ18_28: J18.28 R199.2
NetJ18_30: J18.30 J18.32 J18.34 R200.2
NetJ18_38: J18.38 R210.2
NetJ18_40: J18.40 R212.2
NetJ18_42: J18.42 R213.2
NetJ18_44: J18.44 R215.2
NetR139_1: R139.1 TP51.1
NetR140_2: R140.2 TP50.1
NetR144_1: R144.1 TP21.1
NetR145_1: R145.1 TP20.1
NetR146_2: R146.2 TP24.1
NetR147_1: R147.1 TP19.1
NetR148_2: R148.2 TP23.1
NetR149_1: R149.1 TP18.1
NetR150_2: R150.2 TP22.1

Not connected (* = marked no-connect by the designer): J3 2 3 4 5 6 7 8 9 10 11 12 13 14 15 17 19 21 23 25 26 27 29 31 33 35 36 37 39 41 43 45 46 47 48 49 51 52 53 54 55 57; J18 2 3 4 5 6 7 8 9 10 11 12 13 14 15 17 19 21 23 25 26 27 29 31 33 35 36 37 39 41 43 45 46 47 48 49 51 52 53 54 55 57

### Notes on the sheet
- (near J1) BBB (P8)
- TI-PHI PLATFORM INTERFACE
  WITHOUT  ISOLATION
- 1P8V
- (near J2) BBB (P9)
- (near J3) EVM1_PRESENTn
- TI-PHI PLATFORM INTERFACE WITH ISOLATION
- (near L1) 5V INPUT SUPPLY FOR  BBB
- BEAGLE BONE BLACK INTERFACE WITH ISOLATION

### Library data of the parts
C75 C78 C220 C222 = GRM155R71C104KA88D: CAP, CERM, 0.1 µF, 16 V, +/- 10%, X7R, 0402; Manufacturer: MuRata; Polarized: N; CompType: Capacitor; Value: 0.1uF; U/M: EA; Cap_F: 0.0000001; Tolerance_%: 10; Value1: Unknown; VDC_V: 16; Value2: 16V; TaMin_C: -55; TaMax_C: 125
C82-C84 C87 C89 C90 = GRM21BR71A106KE51L: CAP, CERM, 10 µF, 10 V, +/- 10%, X7R, 0805; Manufacturer: MuRata; Polarized: N; CompType: Capacitor; Value: 10uF; U/M: EA; Cap_F: 0.00001; Tolerance_%: 10; ESR_ohm: 0.003; Value1: 0.003 ohm; Value2: 10V; TaMin_C: -55; TaMax_C: 125; Cap_Case: 0805; AEC Category: Q200
J1 J2 = TSW-123-07-G-D: Header, 2.54 mm, 23x2, Gold, TH; Manufacturer: Samtec; SymbolCreator: Altium; U/M: EA
J3 J18 = QTH-030-01-L-D-A: Header(Shrouded), 19.7mil, 30x2, Gold, SMT; Manufacturer: Samtec; SymbolCreator: Altium; U/M: EA
J4 J21 = 61300211121: Header, 2.54 mm, 2x1, Gold, TH; Manufacturer: Wurth Elektronik eiSos; SymbolCreator: a0412235; U/M: EA
L1 = HZ0805E601R-10: Ferrite Bead, 600 ohm @ 100 MHz, 0.5 A, 0805; Manufacturer: Laird-Signal Integrity Products; Imax_A: 0.5; DCR_ohm: 0.3; Value1: 0.3 ohm; Value2: 0.5A; ZTyp@100MHz_Ohm: 600
R1-R44 R123-R152 = CRCW040210R0FKED: RES, 10.0, 1%, 0.063 W, 0402; Manufacturer: Vishay-Dale; CompType: Resistor; Value: 10.0; Res_ohm: 10; Value_Code: 10R0; Tolerance_%: 1; Power_W: 0.063; Value2: 0.063W; VDC_V: 50; TempCo: 100 ppm/C; EIA_Code: E96; U/M: EA
R160 R162-R164 R166 R169-R173 R175 R186 R189 R190 R193 R195 R199 R200 R210 R212 R213 R215 = ERJ-2GE0R00X: RES, 0, 5%, 0.063 W, 0402; Manufacturer: Panasonic; CompType: Resistor; Value: 0; Value_Code: 0000; Tolerance_%: 5; Power_W: 0.063; Value2: 0.063W; VDC_V: 50; TempCo: 600 ppm/C; EIA_Code: E24; U/M: EA; AEC Category: Q200
R246 R251 = CRCW060310K0FKEA: RES, 10.0 k, 1%, 0.1 W, 0603; Manufacturer: Vishay-Dale; CompType: Resistor; Value: 10.0k; Res_ohm: 10000; Value_Code: 10k0; Tolerance_%: 1; Power_W: 0.1; Value2: 0.1W; VDC_V: 75; TempCo: 100 ppm/C; EIA_Code: E96; U/M: EA
TP15 TP18-TP25 TP30 TP31 TP50 TP51 = TP-025-SMT: Test Point, O.025"; Manufacturer: STD; Value: STD
U21 U28 = BR24G32FVT-3AGE2: I2C BUS EEPROM (2-Wire), TSSOP-B8; Manufacturer: Rohm; SymbolCreator: a0411947

## Sheet TIDA-00732_Isolator.SchDoc: Power & Isolators
size 431 x 279 mm; Date: Not shown in title block; ApprovedBy: Not shown in title block; CheckedBy: Not shown in title block; Author: Not shown in title block; CompanyName: Not shown in title block; DrawnBy: Anbu Mani; Engineer: Not shown in title block; Organization: Not shown in title block; Address1: Not shown in title block; Address2: Not shown in title block; Address3: Not shown in title block; Address4: Not shown in title block; DocumentNumber: 1; Revision: Use project parameter SCH_Rev; SheetNumber: 3; SheetTotal: 10; PageSetup: Record=PageOptions¦CenterHorizontal=True¦CenterVertical=True¦PrintScale=1.00¦XCorrection=1.00¦YCorrection=1.00¦PrintKind=0¦BorderSize=5000000¦LeftOffset=0¦BottomOffset=0¦Orientation=2¦PaperLength=1000¦PaperWidth=1000¦Scale=100¦PaperSource=15¦PrintQuality=600¦MediaType=1¦DitherType=10¦PaperKind=Letter¦PrintScaleMode=1
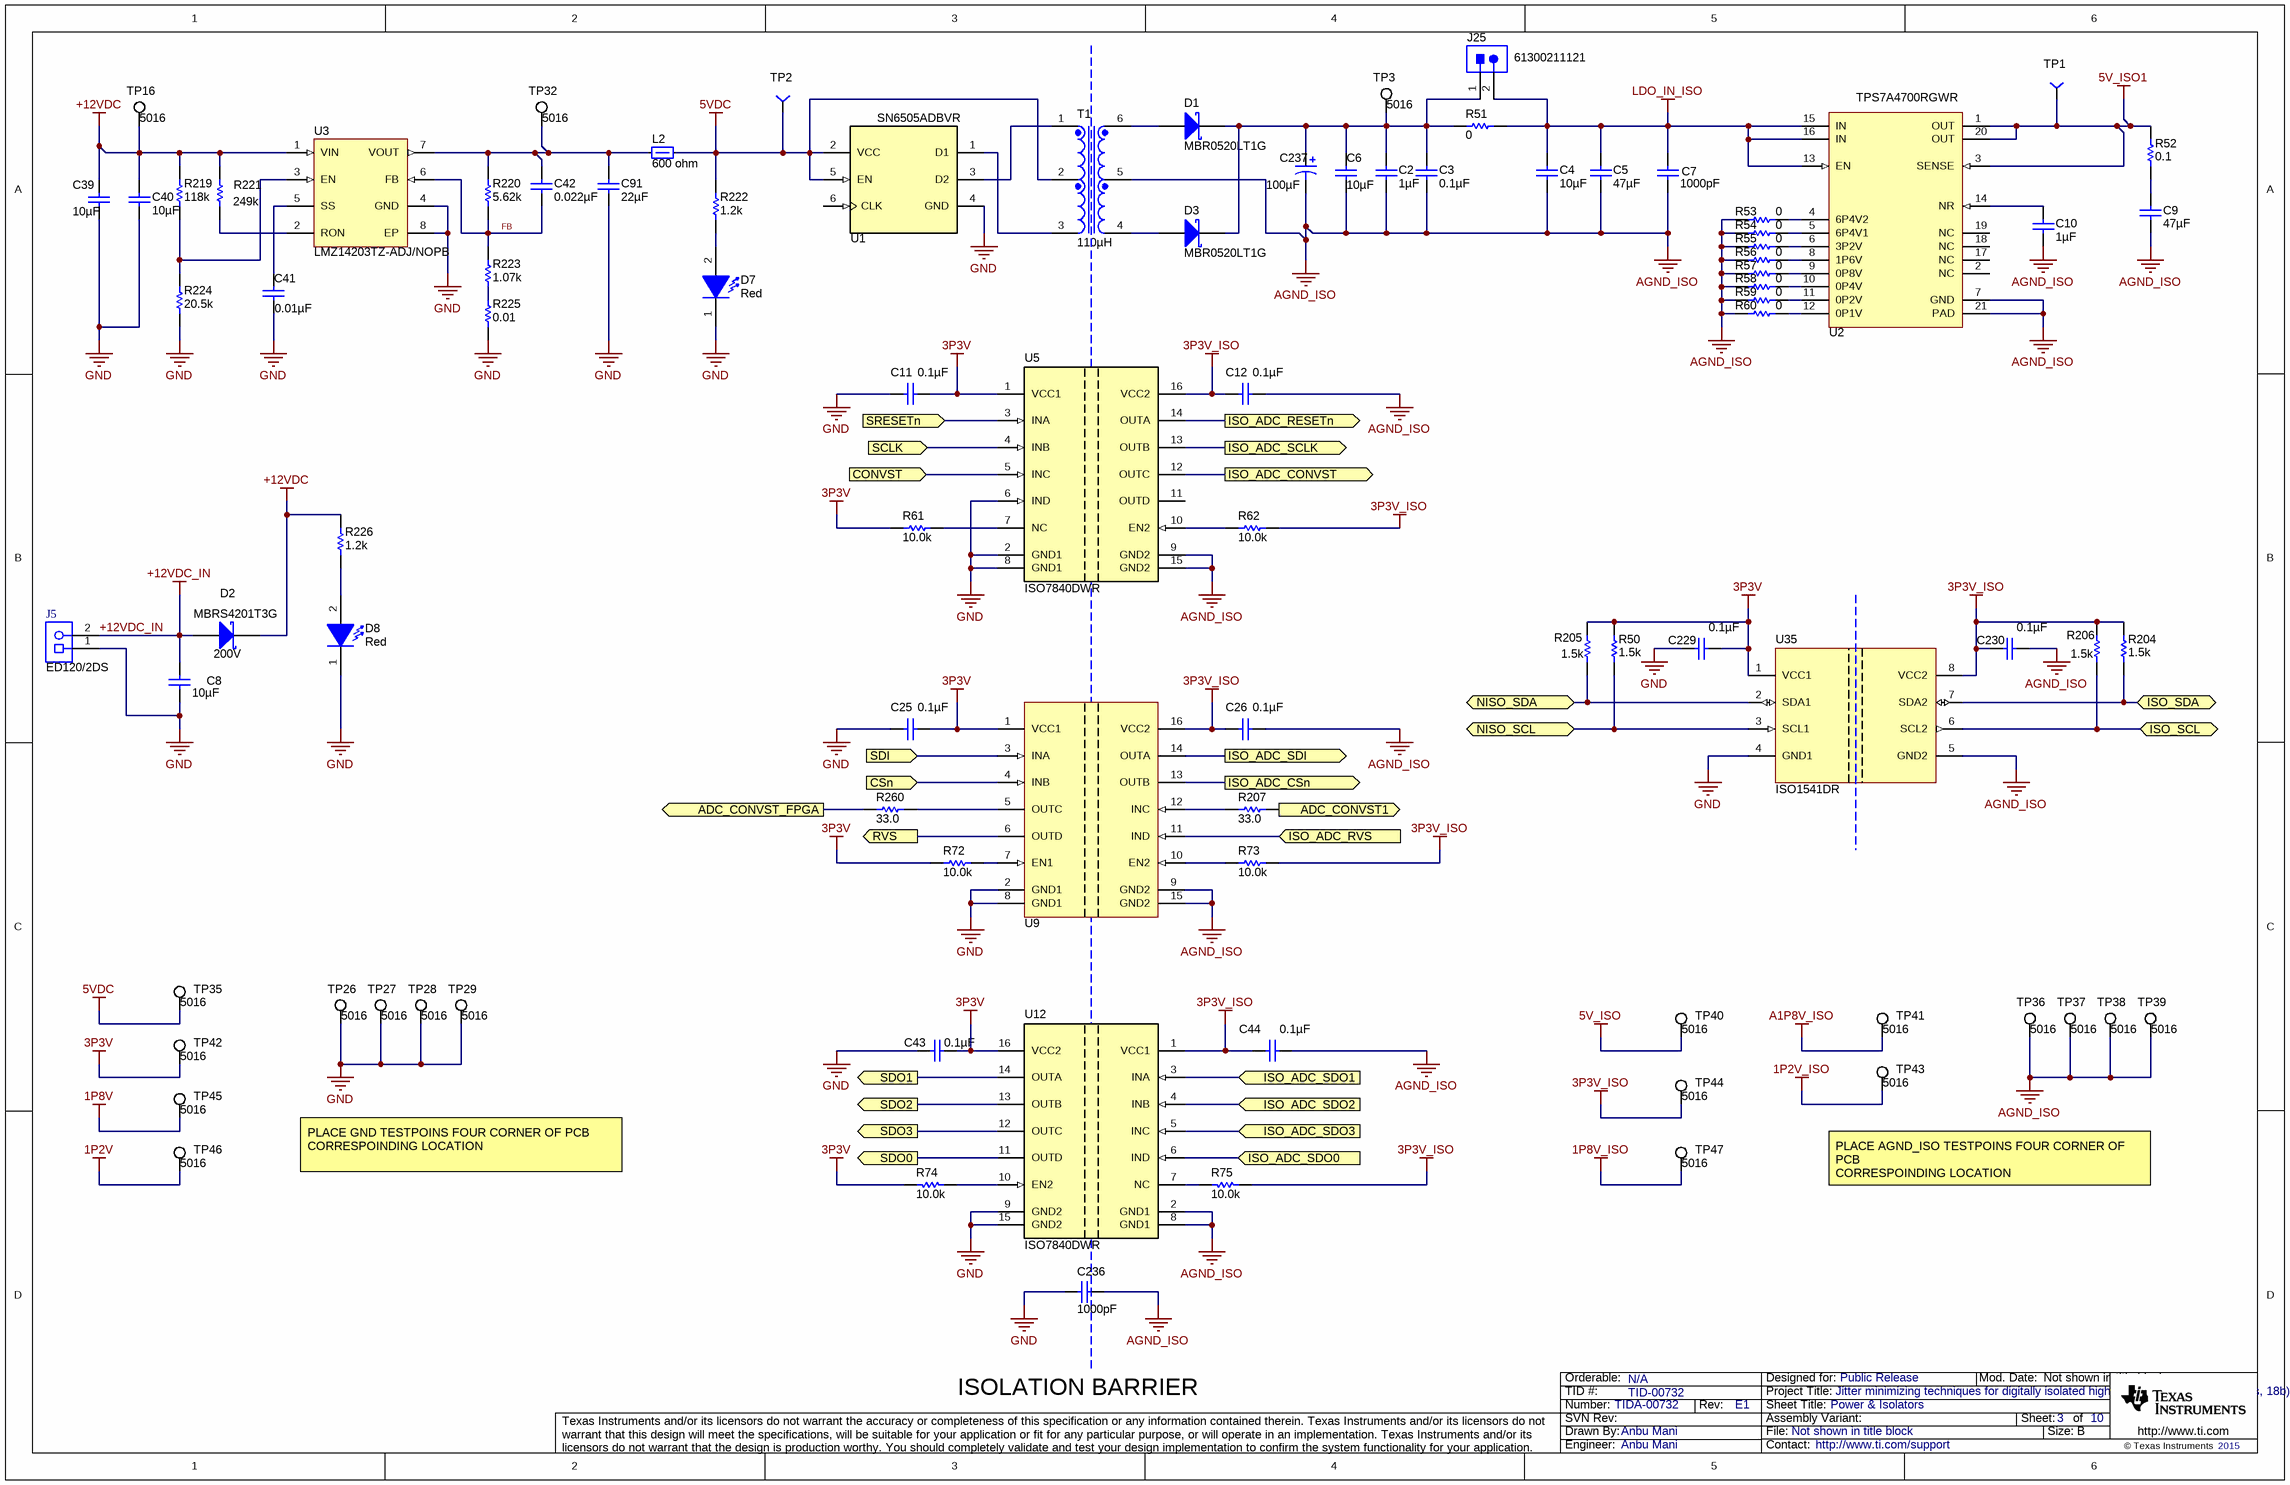
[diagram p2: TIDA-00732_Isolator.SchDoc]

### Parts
C2  ValueDisplayed: 1µF  [0603]  (hidden comment: GRM188R71E105KA12D)
C3  ValueDisplayed: 0.1µF  [0402]  (hidden comment: GRM155R71C104KA88D)
C4  ValueDisplayed: 10µF  [0805_HV]  (hidden comment: GRM21BR71A106KE51L)
C5  ValueDisplayed: 47µF  [1206_190]  (hidden comment: C3216X5R1E476M160AC)
C6  ValueDisplayed: 10µF  [1206_190]  (hidden comment: C3216X7R1E106M160AE)
C7  ValueDisplayed: 1000pF  [0603]  (hidden comment: GRM1885C1H102FA01J)
C8  ValueDisplayed: 10µF  [1206_190]  (hidden comment: C3216X7R1E106M160AE)
C9  ValueDisplayed: 47µF  [1206_190]  (hidden comment: C3216X5R1E476M160AC)
C10  ValueDisplayed: 1µF  [0603]  (hidden comment: GRM188R71E105KA12D)
C11  ValueDisplayed: 0.1µF  [0402]  (hidden comment: GRM155R71C104KA88D)
C12  ValueDisplayed: 0.1µF  [0402]  (hidden comment: GRM155R71C104KA88D)
C25  ValueDisplayed: 0.1µF  [0402]  (hidden comment: GRM155R71C104KA88D)
C26  ValueDisplayed: 0.1µF  [0402]  (hidden comment: GRM155R71C104KA88D)
C39  ValueDisplayed: 10µF  [1210_280]  (hidden comment: UMK325AB7106KM-T)
C40  ValueDisplayed: 10µF  [1210_280]  (hidden comment: UMK325AB7106KM-T)
C41  ValueDisplayed: 0.01µF  [0603]  (hidden comment: C0603C103J5RACTU)
C42  ValueDisplayed: 0.022µF  [0805_HV]  (hidden comment: 08055C223KAT2A)
C43  ValueDisplayed: 0.1µF  [0402]  (hidden comment: GRM155R71C104KA88D)
C44  ValueDisplayed: 0.1µF  [0402]  (hidden comment: GRM155R71C104KA88D)
C91  ValueDisplayed: 22µF  [1210]  (hidden comment: C3225X5R1A226M)
C229  ValueDisplayed: 0.1µF  [0402]  (hidden comment: GRM155R71C104KA88D)
C230  ValueDisplayed: 0.1µF  [0402]  (hidden comment: GRM155R71C104KA88D)
C236  ValueDisplayed: 1000pF  [1206_190]  (hidden comment: 202R18W102KV4E)
C237  ValueDisplayed: 100µF  [7343-43]  (hidden comment: 293D107X9020E2TE3)
D1  MBR0520LT1G  [SOD-123]
D2  value 200V  [SMC]  (hidden comment: MBRS4201T3G)
D3  MBR0520LT1G  [SOD-123]
D7  value Red  [WL-SMCW_RED]  (hidden comment: 150060RS75000)
D8  value Red  [WL-SMCW_RED]  (hidden comment: 150060RS75000)
J5  ED120/2DS  [CONN_ED120-2DS]
J25  61300211121  [WURTH_61300211121]
L2  value 600 ohm  [0805_HV]  (hidden comment: MPZ2012S601A)
R50  ValueDisplayed: 1.5k  [0805_HV]  (hidden comment: CRCW08051K50JNEA)
R51  ValueDisplayed: 0  [1206]  (hidden comment: CRCW12060000Z0EA)
R52  ValueDisplayed: 0.1  [0603]  (hidden comment: ERJ-3RSFR10V)
R53  ValueDisplayed: 0  [0402]  (hidden comment: ERJ-2GE0R00X)
R54  ValueDisplayed: 0  [0402]  (hidden comment: ERJ-2GE0R00X)
R55  ValueDisplayed: 0  [0402]  (hidden comment: ERJ-2GE0R00X)
R56  ValueDisplayed: 0  [0402]  (hidden comment: ERJ-2GE0R00X)
R57  ValueDisplayed: 0  [0402]  (hidden comment: ERJ-2GE0R00X)
R58  ValueDisplayed: 0  [0402]  (hidden comment: ERJ-2GE0R00X)
R59  ValueDisplayed: 0  [0402]  (hidden comment: ERJ-2GE0R00X)
R60  ValueDisplayed: 0  [0402]  (hidden comment: ERJ-2GE0R00X)
R61  ValueDisplayed: 10.0k  [0402]  (hidden comment: ERJ-2RKF1002X)
R62  ValueDisplayed: 10.0k  [0402]  (hidden comment: ERJ-2RKF1002X)
R72  ValueDisplayed: 10.0k  [0402]  (hidden comment: ERJ-2RKF1002X)
R73  ValueDisplayed: 10.0k  [0402]  (hidden comment: ERJ-2RKF1002X)
R74  ValueDisplayed: 10.0k  [0402]  (hidden comment: ERJ-2RKF1002X)
R75  ValueDisplayed: 10.0k  [0402]  (hidden comment: ERJ-2RKF1002X)
R204  ValueDisplayed: 1.5k  [0805_HV]  (hidden comment: CRCW08051K50JNEA)
R205  ValueDisplayed: 1.5k  [0805_HV]  (hidden comment: CRCW08051K50JNEA)
R206  ValueDisplayed: 1.5k  [0805_HV]  (hidden comment: CRCW08051K50JNEA)
R207  ValueDisplayed: 33.0  [0603]  (hidden comment: RC0603FR-0733RL)
R219  value 118k  [0805_HV]  (hidden comment: RT0805BRD07118KL)
R220  ValueDisplayed: 5.62k  [0805_HV]  (hidden comment: RT0805BRD075K62L)
R221  value 249k  [0805_HV]  (hidden comment: CRCW0805249KFKEA)
R222  ValueDisplayed: 1.2k  [0603]  (hidden comment: CRCW06031K20JNEA)
R223  ValueDisplayed: 1.07k  [0805_HV]  (hidden comment: RT0805BRD071K07L)
R224  ValueDisplayed: 20.5k  [0805_HV]  (hidden comment: CRCW080520K5FKEA)
R225  ValueDisplayed: 0.01  [0805_HV]  (hidden comment: WSL0805R0100FEA18)
R226  ValueDisplayed: 1.2k  [0603]  (hidden comment: CRCW06031K20JNEA)
R260  ValueDisplayed: 33.0  [0603]  (hidden comment: RC0603FR-0733RL)
T1  ValueDisplayed: 110µH  [Wurth_750315240]  (hidden comment: 750315240)
TP1  TP1_PD40_D0.5_S50  [TP-040_RND]  (value not drawn)
TP2  TP1_PD40_D0.5_S50  [TP-040_RND]  (value not drawn)
TP3  5016  [Testpoint_Keystone_Compact]
TP16  5016  [Testpoint_Keystone_Compact]
TP26  5016  [Testpoint_Keystone_Compact]
TP27  5016  [Testpoint_Keystone_Compact]
TP28  5016  [Testpoint_Keystone_Compact]
TP29  5016  [Testpoint_Keystone_Compact]
TP32  5016  [Testpoint_Keystone_Compact]
TP35  5016  [Testpoint_Keystone_Compact]
TP36  5016  [Testpoint_Keystone_Compact]
TP37  5016  [Testpoint_Keystone_Compact]
TP38  5016  [Testpoint_Keystone_Compact]
TP39  5016  [Testpoint_Keystone_Compact]
TP40  5016  [Testpoint_Keystone_Compact]
TP41  5016  [Testpoint_Keystone_Compact]
TP42  5016  [Testpoint_Keystone_Compact]
TP43  5016  [Testpoint_Keystone_Compact]
TP44  5016  [Testpoint_Keystone_Compact]
TP45  5016  [Testpoint_Keystone_Compact]
TP46  5016  [Testpoint_Keystone_Compact]
TP47  5016  [Testpoint_Keystone_Compact]
U1  SN6505ADBVR  [DBV0006A_N]
U2  TPS7A4700RGWR  [RGW0020A]
U3  LMZ14203TZ-ADJ/NOPB  [TZA07A_V]
U5  ISO7840DWR  [DW0016B_N]
U9  ISO7842DWR  [DW0016B_N]  (value not drawn)
U12  ISO7840DWR  [DW0016B_N]
U35  ISO1541DR  [D0008A_N]

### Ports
ADC_CONVST1 (in), ADC_CONVST_FPGA (out), CONVST (in), CSn (in), ISO_ADC_CONVST (out), ISO_ADC_CSn (out), ISO_ADC_RESETn (out), ISO_ADC_RVS (in), ISO_ADC_SCLK (out), ISO_ADC_SDI (out), ISO_ADC_SDO0 (in), ISO_ADC_SDO1 (in), ISO_ADC_SDO2 (in), ISO_ADC_SDO3 (in), ISO_SCL (bidir), ISO_SDA (bidir), NISO_SCL (bidir), NISO_SDA (bidir), RVS (out), SCLK (in), SDI (in), SDO0 (out), SDO1 (out), SDO2 (out), SDO3 (out), SRESETn (in)

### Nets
1P2V: TP46.1
1P2V_ISO: TP43.1
1P8V: TP45.1
1P8V_ISO: TP47.1
3P3V: C11.2 C25.2 C43.1 C229.2 R50.2 R61.1 R72.1 R74.2 R205.2 TP42.1 U5.1(VCC1) U9.1(VCC1) U12.16(VCC2) U35.1(VCC1)
3P3V_ISO: C12.1 C26.1 C44.2 C230.1 R62.2 R73.2 R75.1 R204.2 R206.2 TP44.1 U5.16(VCC2) U9.16(VCC2) U12.1(VCC1) U35.8(VCC2)
5V_ISO: TP40.1
5V_ISO1: R52.2 TP1.1 U2.1(OUT) U2.3(SENSE) U2.20(OUT)
5VDC: L2.2 R222.2 T1.2 TP2.1 TP35.1 U1.2(VCC) U1.5(EN)
+12VDC: C39.1 C40.1 D2.1(K) R219.2 R221.2 R226.2 TP16.1 U3.1(VIN)
+12VDC_IN: C8.1 D2.2(A) J5.2
A1P8V_ISO: TP41.1
AGND_ISO: C2.2 C3.1 C4.2 C5.2 C6.2 C7.2 C9.2 C10.1 C12.2 C26.2 C44.1 C230.2 C236.1 C237.2(-) R53.1 R54.1 R55.1 R56.1 R57.1 R58.1 R59.1 R60.1 T1.5 TP36.1 TP37.1 TP38.1 TP39.1 U2.7(GND) U2.21(PAD) U5.9(GND2) U5.15(GND2) U9.9(GND2) U9.15(GND2) U12.2(GND1) U12.8(GND1) U35.5(GND2)
GND: C8.2 C11.1 C25.1 C39.2 C40.2 C41.2 C43.2 C91.2 C229.1 C236.2 D7.1(K) D8.1(K) J5.1 R224.1 R225.1 TP26.1 TP27.1 TP28.1 TP29.1 U1.4(GND) U3.4(GND) U3.8(EP) U5.2(GND1) U5.6(IND) U5.8(GND1) U9.2(GND1) U9.8(GND1) U12.9(GND2) U12.15(GND2) U35.4(GND1)
LDO_IN_ISO: C4.1 C5.1 C7.1 J25.2 R51.2 U2.13(EN) U2.15(IN) U2.16(IN)
ADC_CONVST1: R207.2 ; port ADC_CONVST1
ADC_CONVST_FPGA: R260.1 ; port ADC_CONVST_FPGA
CONVST: U5.5(INC) ; port CONVST
CSn: U9.4(INB) ; port CSn
FB: C42.2 R220.1 R223.2 U3.6(FB)
ISO_ADC_CONVST: U5.12(OUTC) ; port ISO_ADC_CONVST
ISO_ADC_CSn: U9.13(OUTB) ; port ISO_ADC_CSn
ISO_ADC_RESETn: U5.14(OUTA) ; port ISO_ADC_RESETn
ISO_ADC_RVS: U9.11(IND) ; port ISO_ADC_RVS
ISO_ADC_SCLK: U5.13(OUTB) ; port ISO_ADC_SCLK
ISO_ADC_SDI: U9.14(OUTA) ; port ISO_ADC_SDI
ISO_ADC_SDO0: U12.6(IND) ; port ISO_ADC_SDO0
ISO_ADC_SDO1: U12.3(INA) ; port ISO_ADC_SDO1
ISO_ADC_SDO2: U12.4(INB) ; port ISO_ADC_SDO2
ISO_ADC_SDO3: U12.5(INC) ; port ISO_ADC_SDO3
ISO_SCL: R206.1 U35.6(SCL2) ; port ISO_SCL
ISO_SDA: R204.1 U35.7(SDA2) ; port ISO_SDA
NISO_SCL: R50.1 U35.3(SCL1) ; port NISO_SCL
NISO_SDA: R205.1 U35.2(SDA1) ; port NISO_SDA
RVS: U9.6(OUTD) ; port RVS
SCLK: U5.4(INB) ; port SCLK
SDI: U9.3(INA) ; port SDI
SDO0: U12.11(OUTD) ; port SDO0
SDO1: U12.14(OUTA) ; port SDO1
SDO2: U12.13(OUTB) ; port SDO2
SDO3: U12.12(OUTC) ; port SDO3
SRESETn: U5.3(INA) ; port SRESETn
NetC2_1: C2.1 C3.2 C6.1 C237.1(+) D1.1(K) D3.1(K) J25.1 R51.1 TP3.1
NetC9_1: C9.1 R52.1
NetC10_2: C10.2 U2.14(NR)
NetC41_1: C41.1 U3.5(SS)
NetC42_1: C42.1 C91.1 L2.1 R220.2 TP32.1 U3.7(VOUT)
NetD1_2: D1.2(A) T1.6
NetD3_2: D3.2(A) T1.4
NetD7_2: D7.2(A) R222.1
NetD8_2: D8.2(A) R226.1
NetR53_2: R53.2 U2.4(6P4V2)
NetR54_2: R54.2 U2.5(6P4V1)
NetR55_2: R55.2 U2.6(3P2V)
NetR56_2: R56.2 U2.8(1P6V)
NetR57_2: R57.2 U2.9(0P8V)
NetR58_2: R58.2 U2.10(0P4V)
NetR59_2: R59.2 U2.11(0P2V)
NetR60_2: R60.2 U2.12(0P1V)
NetR61_2: R61.2 U5.7(NC)
NetR62_1: R62.1 U5.10(EN2)
NetR72_2: R72.2 U9.7(EN1)
NetR73_1: R73.1 U9.10(EN2)
NetR74_1: R74.1 U12.10(EN2)
NetR75_2: R75.2 U12.7(NC)
NetR207_1: R207.1 U9.12(INC)
NetR219_1: R219.1 R224.2 U3.3(EN)
NetR221_1: R221.1 U3.2(RON)
NetR223_1: R223.1 R225.2
NetR260_2: R260.2 U9.5(OUTC)
NetT1_1: T1.1 U1.3(D2)
NetT1_3: T1.3 U1.1(D1)

Not connected (* = marked no-connect by the designer): U1 6(CLK); U2 2(NC) 17(NC) 18(NC) 19(NC); U5 11(OUTD)

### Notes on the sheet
- PLACE GND TESTPOINS FOUR CORNER OF PCB
  CORRESPOINDING LOCATION
- PLACE AGND_ISO TESTPOINS FOUR CORNER OF PCB
  CORRESPOINDING LOCATION
- ISOLATION BARRIER

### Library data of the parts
C2 = GRM188R71E105KA12D: CAP, CERM, 1 µF, 25 V, +/- 10%, X7R, 0603; Manufacturer: MuRata; Polarized: N; CompType: Capacitor; Value: 1uF; U/M: EA; Cap_F: 0.000001; Tolerance_%: 10; Value1: Unknown; VDC_V: 25; Value2: 25V; TaMin_C: -55; TaMax_C: 125
C3 C11 C12 C25 C26 C43 C44 C229 C230 = GRM155R71C104KA88D: as C75 on sheet TIDA-00732_Connector
C4 = GRM21BR71A106KE51L: as C82 on sheet TIDA-00732_Connector
C5 C9 = C3216X5R1E476M160AC: CAP, CERM, 47 µF, 25 V, +/- 20%, X5R, 1206_190; Manufacturer: TDK; Polarized: N; CompType: Capacitor; Value: 47uF; U/M: EA; Cap_F: 0.000047; Tolerance_%: 20; Value1: Unknown; VDC_V: 25; Value2: 25V; TaMin_C: -55; TaMax_C: 85; Cap_Case: 1206; AEC Category: Q200
C6 C8 = C3216X7R1E106M160AE: CAP, CERM, 10 µF, 25 V, +/- 20%, X7R, 1206_190; Manufacturer: TDK; Polarized: N; CompType: Capacitor; Value: 10uF; U/M: EA; Cap_F: 0.00001; Tolerance_%: 20; Value1: Unknown; VDC_V: 25; Value2: 25V; TaMin_C: -55; TaMax_C: 125; Cap_Case: 1206; AEC Category: Q200
C7 = GRM1885C1H102FA01J: CAP, CERM, 1000 pF, 50 V, +/- 1%, C0G/NP0, 0603; Manufacturer: MuRata; Polarized: N; CompType: Capacitor; Value: 1000pF; U/M: EA; Cap_F: 0.000000001; Tolerance_%: 1; Value1: Unknown; VDC_V: 50; Value2: 50V; TaMin_C: -55; TaMax_C: 125; AEC Category: Q200
C10 = GRM188R71E105KA12D: CAP, CERM, 1 µF, 25 V, +/- 10%, X7R, 0603; Manufacturer: MuRata; Polarized: N; CompType: Capacitor; Value: 1uF; U/M: EA; Cap_F: 0.000001; Tolerance_%: 10; Value1: Unknown; VDC_V: 25; Value2: 25V; TaMin_C: -55; TaMax_C: 125; AEC Category: Q200
C39 C40 = UMK325AB7106KM-T: CAP, CERM, 10 µF, 50 V, +/- 10%, X7R, 1210; Manufacturer: Taiyo Yuden; Polarized: N; CompType: Capacitor; Value: 10uF; U/M: EA; Cap_F: 0.00001; Tolerance_%: 10; Value1: Unknown; VDC_V: 50; Value2: 50V; TaMin_C: -55; TaMax_C: 125; Cap_Case: 1210; AEC Category: Q200
C41 = C0603C103J5RACTU: CAP, CERM, 0.01uF, 50V, +/-5%, X7R, 0603; Manufacturer: Kemet; Polarized: N; CompType: Capacitor; U/M: EA; Cap_F: 0.00000001; Tolerance_%: 5; Value1: Unknown; VDC_V: 50; TaMin_C: -55; TaMax_C: 125
C42 = 08055C223KAT2A: CAP, CERM, 0.022uF, 50V, +/-10%, X7R, 0805; Manufacturer: AVX; Polarized: N; CompType: Capacitor; U/M: EA; Cap_F: 0.000000022; Tolerance_%: 10; ESR_Ohm: 0.052; Value1: 0.052 ohm; VDC_V: 50; TaMin_C: -55; TaMax_C: 125; Cap_Case: 0805
C91 = C3225X5R1A226M: CAP, CERM, 22uF, 10V, +/-20%, X5R, 1210; Manufacturer: TDK; Polarized: N; CompType: Capacitor; U/M: EA; Cap_F: 0.000022; Tolerance_%: 20; ESR_Ohm: 0.002; Value1: 0.002 ohm; VDC_V: 10; IRMS_A: 3.2; TaMin_C: -55; TaMax_C: 85
C236 = 202R18W102KV4E: CAP, CERM, 1000 pF, 2000 V, +/- 10%, X7R, 1206_190; Manufacturer: Johanson Technology; Polarized: N; CompType: Capacitor; Value: 1000pF; U/M: EA; Cap_F: 0.000000001; Tolerance_%: 10; Value1: Unknown; VDC_V: 2000; Value2: 2000V; TaMin_C: -55; TaMax_C: 125; Cap_Case: 1206; AEC Category: Q200
C237 = 293D107X9020E2TE3: CAP, TA, 100 µF, 20 V, +/- 10%, 0.5 ohm, SMD; Manufacturer: Vishay-Sprague; Polarized: Y; CompType: Capacitor; Value: 100uF; U/M: EA; Cap_F: 0.0001; Tolerance_%: 10; Value1: 0.5 ohm; VDC_V: 20; Value2: 20V; ESR_ohm: 0.5; IRMS_A: 0.57; TaMin_C: -55; TaMax_C: 125; Cap_Case: E; AEC Category: Q200
D1 D3 = MBR0520LT1G: Diode, Schottky, 20 V, 0.5 A, SOD-123; Manufacturer: ON Semiconductor; U/M: EA; Vf_V: 0.385; Value: 20V; Value1: 0.5A; Value2: 0.385V; Io_A: 0.5; Vr_V: 20; TJmax_C: 125; RJC_CperW: 150; AEC Category: Q101
D2 = MBRS4201T3G: Diode, Schottky, 200V, 4A, SMC; Manufacturer: ON Semiconductor; Io_A: 4
D7 D8 = 150060RS75000: LED, Red, SMD; Manufacturer: Wurth Elektronik; Type: AlInGaP; Vf_V: 2; Value2: 2V; Io_A: 0.03; Vr_V: 5; Tjmax_C: 85; Power_TotalModule: 0.072; Value1: 0.072W; Angle: 140; U/M: EA
J5 = ED120/2DS: TERMINAL BLOCK 5.08MM VERT 2POS, TH; Manufacturer: On-Shore Technology; SymbolCreator: a0412235; U/M: EA
J25 = 61300211121: as J4 on sheet TIDA-00732_Connector
L2 = MPZ2012S601A: Ferrite Bead, 600 ohm @ 100MHz, 2A, 0805; Manufacturer: TDK; Imax_A: 2; DCR_ohm: 0.1; Value1: 0.1 ohm; ZTyp@100MHz_Ohm: 600
R50 R204-R206 = CRCW08051K50JNEA: RES, 1.5 k, 5%, 0.125 W, 0805; Manufacturer: Vishay-Dale; CompType: Resistor; Value: 1.5k; Res_ohm: 1500; Value_Code: 1k50; Tolerance_%: 5; Power_W: 0.125; Value2: 0.125W; VDC_V: 150; TempCo: 200 ppm/C; EIA_Code: E24; U/M: EA; AEC Category: Q200
R51 = CRCW12060000Z0EA: RES, 0, 5%, 0.25 W, 1206; Manufacturer: Vishay-Dale; CompType: Resistor; Value: 0; Value_Code: 0000; Tolerance_%: 5; Power_W: 0.25; Value2: 0.25W; VDC_V: 200; TempCo: 200 ppm/C; EIA_Code: E24; U/M: EA; AEC Category: Q200
R52 = ERJ-3RSFR10V: RES, 0.1, 1%, 0.1 W, 0603; Manufacturer: Panasonic; CompType: Resistor; Value: 0.1; Value_Code: R100; Tolerance_%: 1; Value2: 0.1W; TempCo: 300 ppm/C; EIA_Code: E96; U/M: EA; AEC Category: Q200
R53-R60 = ERJ-2GE0R00X: as R160 on sheet TIDA-00732_Connector
R61 R62 R72-R75 = ERJ-2RKF1002X: RES, 10.0 k, 1%, 0.1 W, 0402; Manufacturer: Panasonic; CompType: Resistor; Value: 10.0k; Res_ohm: 10000; Value_Code: 10k0; Tolerance_%: 1; Power_W: 0.1; Value2: 0.1W; VDC_V: 50; TempCo: 100 ppm/C; EIA_Code: E96; U/M: EA; AEC Category: Q200
R207 R260 = RC0603FR-0733RL: RES, 33.0, 1%, 0.1 W, 0603; Manufacturer: Yageo America; CompType: Resistor; Value: 33.0; Res_ohm: 33; Value_Code: 33R0; Tolerance_%: 1; Power_W: 0.1; Value2: 0.1W; VDC_V: 150; TempCo: 200 ppm/C; U/M: EA; AEC Category: Q200
R219 = RT0805BRD07118KL: RES, 118k ohm, 0.1%, 0.125W, 0805; Manufacturer: Yageo America; CompType: Resistor; Res_ohm: 118000; Tolerance_%: 0.1; Power_W: 0.125; VDC_V: 150; TempCo: 25 ppm/C; EIA_Code: E192; U/M: EA
R220 = RT0805BRD075K62L: RES, 5.62 k, 0.1%, 0.125 W, 0805; Manufacturer: Yageo America; CompType: Resistor; Value: 5.62k; Res_ohm: 5620; Value_Code: 5k62; Tolerance_%: 0.1; Power_W: 0.125; Value2: 0.125W; VDC_V: 150; TempCo: 25 ppm/C; EIA_Code: E192; U/M: EA; AEC Category: Q200
R221 = CRCW0805249KFKEA: RES, 249k ohm, 1%, 0.125W, 0805; Manufacturer: Vishay-Dale; CompType: Resistor; Res_ohm: 249000; Tolerance_%: 1; Power_W: 0.125; VDC_V: 150; TempCo: 100 ppm/C; EIA_Code: E96; U/M: EA
R222 R226 = CRCW06031K20JNEA: RES, 1.2 k, 5%, 0.1 W, 0603; Manufacturer: Vishay-Dale; CompType: Resistor; Value: 1.2k; Res_ohm: 1200; Value_Code: 1k20; Tolerance_%: 5; Power_W: 0.1; Value2: 0.1W; VDC_V: 75; TempCo: 200 ppm/C; EIA_Code: E24; U/M: EA; AEC Category: Q200
R223 = RT0805BRD071K07L: RES, 1.07 k, 0.1%, 0.125 W, 0805; Manufacturer: Yageo America; CompType: Resistor; Value: 1.07k; Res_ohm: 1070; Value_Code: 1k07; Tolerance_%: 0.1; Power_W: 0.125; Value2: 0.125W; VDC_V: 150; TempCo: 25 ppm/C; EIA_Code: E192; U/M: EA; AEC Category: Q200
R224 = CRCW080520K5FKEA: RES, 20.5 k, 1%, 0.125 W, 0805; Manufacturer: Vishay-Dale; CompType: Resistor; Value: 20.5k; Res_ohm: 20500; Value_Code: 20k5; Tolerance_%: 1; Power_W: 0.125; Value2: 0.125W; VDC_V: 150; TempCo: 100 ppm/C; EIA_Code: E96; U/M: EA; AEC Category: Q200
R225 = WSL0805R0100FEA18: RES, 0.01, 1%, 0.25 W, 0805; Manufacturer: Vishay-Dale; CompType: Resistor; Value: 0.01; Value_Code: R010; Tolerance_%: 1; Power_W: 0.25; Value2: 0.25W; TempCo: 75 ppm/C; EIA_Code: E96; U/M: EA; AEC Category: Q200
T1 = 750315240: Transformer, 110 uH, SMT; Manufacturer: Wurth Elektronik; SymbolCreator: Altium; Value: 110uH; Lp: 110; DCR_ohm: 0.15
TP1 TP2 = TP-040_RND: Test Point 40mil pad 20mil drill; Manufacturer: STD; Value: STD
TP3 TP16 TP26-TP29 TP32 TP35-TP47 = 5016: Test Point, Compact, SMT; Manufacturer: Keystone; CompType: Test Point Loop; U/M: EA
U1 = SN6505ADBVR: LOW-NOISE 1A TRANSFORMER DRIVERS FOR ISOLATED POWER SUPPLIES, DBV0006A; Alternate PartNumber: SN6505ADBVT; Manufacturer: Texas Instruments; SymbolCreator: Altium; CompType: IC; U/M: EA
U2 = TPS7A4700RGWR: 36-V, 1-A, 4.17-μVRMS, RF LDO Voltage Regulator, RGW0020A; Alternate PartNumber: TPS7A4700RGWT; Manufacturer: Texas Instruments; SymbolCreator: a0412235; CompType: IC; U/M: EA
U3 = LMZ14203TZ-ADJ/NOPB: 3A SIMPLE SWITCHER® Power Module with 42V Maximum Input Voltage, 7-pin TO-PMOD, Pb-Free; Manufacturer: Texas Instruments; PackageTopMarking: NSUZXYTTE#*LMZ14203*TZ-ADJ; PowerWise: Y
U5 U12 = ISO7840DWR: High-Performance, 8000 VPK Reinforced Quad-Channel Digital Isolator, DW0016B; Manufacturer: Texas Instruments; SymbolCreator: a0411947; CompType: IC; U/M: EA
U9 = ISO7842DWR: High-Performance, 8000 VPK Reinforced Quad Channel Digital Isolator, DW0016B; Manufacturer: Texas Instruments; SymbolCreator: Altium; CompType: IC; U/M: EA
U35 = ISO1541DR: Low-Power Bidirectional I2C Isolators, D0008A; Manufacturer: Texas Instruments; SymbolCreator: a0411947; CompType: IC; U/M: EA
